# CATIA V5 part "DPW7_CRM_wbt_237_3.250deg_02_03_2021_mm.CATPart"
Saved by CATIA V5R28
Part number: DPW7_CRM_wbt_237_3.250deg_02_03_2021
Bounding box of the stored display mesh (mm): x 2349.5 to 66711.891, y 0 to 29534.133, z 2310.119 to 8715.756
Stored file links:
  Z:\Scratch\04_CAD_Allgemein\Flight2Jig\Output\DPW-7\CATPart\DPW7_CRM_wbt_182_3.250deg_02_03_2021.CATPart
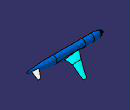
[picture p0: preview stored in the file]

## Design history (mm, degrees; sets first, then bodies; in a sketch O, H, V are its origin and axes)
Set1
  DatumSurface1 "Clean_Wing"
  DatumSurface2 "Fuselage"
  DatumSurface3 "HTP"
  DatumSurface4 "Symmetry"
  DatumSurface5 "Farfield"
Body1 (main body)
